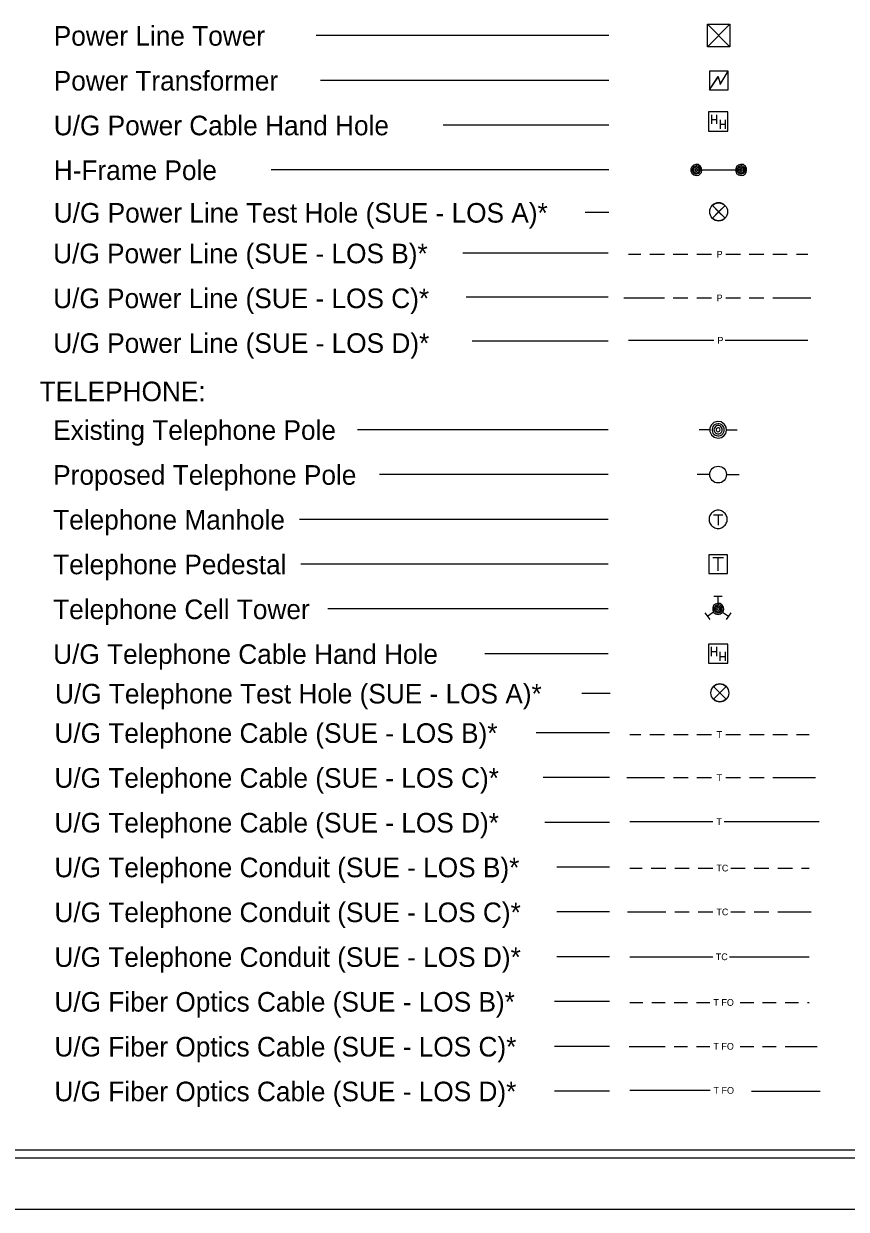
# Model space of a CAD drawing. Extents: x 2594871.4 to 2594905.1, y 784137.6 to 784159.6.
# Drawn here: x 2594889.82 to 2594897.02, y 784137.56 to 784147.95 of the extents above; entities that cross this region are included whole.
import ezdxf

# ---------------------------------------------------------------- set-up
doc = ezdxf.new("R2010")
doc.units = 0
for name, color, linetype in [('Default', 7, 'Continuous'), ('Sheet Plot Border Inside CELL', 7, 'Continuous'), ('Sheet Plot Border Outside CELL', 7, 'Continuous'), ('Sheet Symbology CELL', 7, 'Continuous')]:
    doc.layers.add(name, color=color, linetype=linetype)

msp = doc.modelspace()

# ---------------------------------------------------------------- linework, layer by layer
at = {"layer": 'Default'}
for p, q in [((2594896, 784147.941), (2594895.804, 784147.745)), ((2594896, 784147.745), (2594895.804, 784147.941)), ((2594894.94, 784147.842), (2594892.377, 784147.842)), ((2594894.94, 784147.45), (2594892.417, 784147.45)), ((2594895.837, 784147.148), (2594895.837, 784147.069)), ((2594895.883, 784147.148), (2594895.883, 784147.069)), ((2594894.94, 784147.058), (2594893.491, 784147.058)), ((2594895.837, 784147.108), (2594895.883, 784147.108)), ((2594895.913, 784147.105), (2594895.913, 784147.026)), ((2594895.913, 784147.065), (2594895.958, 784147.065)), ((2594895.958, 784147.105), (2594895.958, 784147.026)), ((2594894.94, 784146.666), (2594891.984, 784146.666)), ((2594895.706, 784146.666), (2594896.098, 784146.666)), ((2594894.94, 784146.293), (2594894.732, 784146.293)), ((2594894.935, 784145.937), (2594893.662, 784145.937)), ((2594895.112, 784145.927), (2594895.22, 784145.927)), ((2594895.298, 784145.927), (2594895.426, 784145.927)), ((2594895.504, 784145.927), (2594895.632, 784145.927)), ((2594895.71, 784145.927), (2594895.837, 784145.927)), ((2594895.963, 784145.927), (2594896.091, 784145.927)), ((2594896.169, 784145.927), (2594896.296, 784145.927)), ((2594896.375, 784145.927), (2594896.502, 784145.927)), ((2594896.581, 784145.927), (2594896.681, 784145.927)), ((2594894.935, 784145.552), (2594893.692, 784145.552)), ((2594895.072, 784145.545), (2594895.426, 784145.545)), ((2594895.504, 784145.545), (2594895.632, 784145.545)), ((2594895.71, 784145.545), (2594895.837, 784145.545)), ((2594895.963, 784145.545), (2594896.091, 784145.545)), ((2594896.169, 784145.545), (2594896.296, 784145.545)), ((2594896.375, 784145.545), (2594896.709, 784145.545)), ((2594894.935, 784145.167), (2594893.744, 784145.167)), ((2594895.112, 784145.173), (2594895.859, 784145.173)), ((2594895.957, 784145.173), (2594896.681, 784145.173)), ((2594894.935, 784144.39), (2594892.74, 784144.39)), ((2594895.824, 784144.39), (2594895.73, 784144.39)), ((2594895.969, 784144.39), (2594896.063, 784144.39)), ((2594894.935, 784143.997), (2594892.933, 784143.997)), ((2594895.824, 784143.997), (2594895.713, 784143.997)), ((2594895.971, 784143.997), (2594896.081, 784143.997)), ((2594894.935, 784143.605), (2594892.231, 784143.605)), ((2594895.937, 784143.642), (2594895.856, 784143.642)), ((2594895.896, 784143.642), (2594895.896, 784143.553)), ((2594894.935, 784143.213), (2594892.244, 784143.213)), ((2594895.85, 784143.272), (2594895.942, 784143.272)), ((2594895.896, 784143.154), (2594895.896, 784143.272)), ((2594895.86, 784142.931), (2594895.933, 784142.931)), ((2594895.896, 784142.869), (2594895.896, 784142.931)), ((2594894.935, 784142.82), (2594892.479, 784142.82)), ((2594895.827, 784142.727), (2594895.784, 784142.787)), ((2594895.857, 784142.793), (2594895.806, 784142.757)), ((2594895.936, 784142.793), (2594895.987, 784142.757)), ((2594896.008, 784142.787), (2594895.966, 784142.727)), ((2594895.836, 784142.487), (2594895.836, 784142.408)), ((2594895.881, 784142.487), (2594895.881, 784142.408)), ((2594894.935, 784142.428), (2594893.855, 784142.428)), ((2594895.836, 784142.447), (2594895.881, 784142.447)), ((2594895.912, 784142.444), (2594895.912, 784142.365)), ((2594895.912, 784142.404), (2594895.957, 784142.404)), ((2594895.957, 784142.444), (2594895.957, 784142.365)), ((2594894.951, 784142.081), (2594894.703, 784142.081)), ((2594894.946, 784141.736), (2594894.303, 784141.736)), ((2594895.122, 784141.72), (2594895.221, 784141.72)), ((2594895.299, 784141.72), (2594895.427, 784141.72)), ((2594895.505, 784141.72), (2594895.633, 784141.72)), ((2594895.711, 784141.72), (2594895.839, 784141.72)), ((2594895.964, 784141.72), (2594896.092, 784141.72)), ((2594896.17, 784141.72), (2594896.298, 784141.72)), ((2594896.376, 784141.72), (2594896.504, 784141.72)), ((2594896.582, 784141.72), (2594896.692, 784141.72)), ((2594894.946, 784141.343), (2594894.365, 784141.343)), ((2594895.098, 784141.343), (2594895.427, 784141.343)), ((2594895.505, 784141.343), (2594895.633, 784141.343)), ((2594895.711, 784141.343), (2594895.839, 784141.343)), ((2594895.964, 784141.343), (2594896.092, 784141.343)), ((2594896.17, 784141.343), (2594896.298, 784141.343)), ((2594896.376, 784141.343), (2594896.75, 784141.343)), ((2594894.946, 784140.951), (2594894.38, 784140.951)), ((2594895.122, 784140.958), (2594895.851, 784140.958)), ((2594895.949, 784140.958), (2594896.78, 784140.958)), ((2594894.946, 784140.559), (2594894.485, 784140.559)), ((2594895.122, 784140.55), (2594895.232, 784140.55)), ((2594895.31, 784140.55), (2594895.438, 784140.55)), ((2594895.516, 784140.55), (2594895.644, 784140.55)), ((2594895.722, 784140.55), (2594895.85, 784140.55)), ((2594896.007, 784140.55), (2594896.134, 784140.55)), ((2594896.213, 784140.55), (2594896.34, 784140.55)), ((2594896.419, 784140.55), (2594896.546, 784140.55)), ((2594896.625, 784140.55), (2594896.692, 784140.55)), ((2594894.946, 784140.166), (2594894.485, 784140.166)), ((2594895.104, 784140.166), (2594895.438, 784140.166)), ((2594895.516, 784140.166), (2594895.644, 784140.166)), ((2594895.722, 784140.166), (2594895.85, 784140.166)), ((2594896.007, 784140.166), (2594896.134, 784140.166)), ((2594896.213, 784140.166), (2594896.34, 784140.166)), ((2594896.419, 784140.166), (2594896.71, 784140.166)), ((2594894.946, 784139.774), (2594894.485, 784139.774)), ((2594895.122, 784139.773), (2594895.85, 784139.773)), ((2594895.997, 784139.773), (2594896.692, 784139.773)), ((2594894.946, 784139.382), (2594894.463, 784139.382)), ((2594895.122, 784139.373), (2594895.237, 784139.373)), ((2594895.315, 784139.373), (2594895.433, 784139.373)), ((2594895.512, 784139.373), (2594895.629, 784139.373)), ((2594895.708, 784139.373), (2594895.825, 784139.373)), ((2594896.09, 784139.373), (2594896.208, 784139.373)), ((2594896.286, 784139.373), (2594896.404, 784139.373)), ((2594896.483, 784139.373), (2594896.6, 784139.373)), ((2594896.679, 784139.373), (2594896.692, 784139.373)), ((2594894.946, 784138.989), (2594894.463, 784138.989)), ((2594895.119, 784138.989), (2594895.433, 784138.989)), ((2594895.512, 784138.989), (2594895.629, 784138.989)), ((2594895.708, 784138.989), (2594895.825, 784138.989)), ((2594896.09, 784138.989), (2594896.208, 784138.989)), ((2594896.286, 784138.989), (2594896.404, 784138.989)), ((2594896.483, 784138.989), (2594896.763, 784138.989)), ((2594894.946, 784138.597), (2594894.463, 784138.597)), ((2594895.122, 784138.604), (2594895.826, 784138.604)), ((2594896.189, 784138.596), (2594896.79, 784138.596))]:
    msp.add_line(p, q, dxfattribs=at)
for points in [[(2594896, 784147.745), (2594895.804, 784147.745), (2594895.804, 784147.941), (2594896, 784147.941), (2594896, 784147.745), (2594895.804, 784147.745), (2594895.804, 784147.941), (2594896, 784147.941), (2594896, 784147.745)], [(2594895.82, 784147.368), (2594895.897, 784147.479), (2594895.916, 784147.419), (2594895.983, 784147.532)], [(2594895.82, 784147.368), (2594895.898, 784147.484), (2594895.915, 784147.414), (2594895.983, 784147.532)], [(2594895.82, 784147.368), (2594895.983, 784147.368), (2594895.983, 784147.532), (2594895.82, 784147.532), (2594895.82, 784147.368)], [(2594895.813, 784147.004), (2594895.982, 784147.004), (2594895.982, 784147.173), (2594895.813, 784147.173), (2594895.813, 784147.004)], [(2594895.741, 784146.666), (2594895.74, 784146.674), (2594895.737, 784146.682), (2594895.733, 784146.689), (2594895.727, 784146.694), (2594895.72, 784146.698), (2594895.711, 784146.7), (2594895.704, 784146.701), (2594895.695, 784146.699), (2594895.687, 784146.696), (2594895.681, 784146.692), (2594895.676, 784146.685), (2594895.672, 784146.678), (2594895.67, 784146.669), (2594895.67, 784146.662), (2594895.672, 784146.653), (2594895.676, 784146.646), (2594895.681, 784146.639), (2594895.687, 784146.635), (2594895.695, 784146.632), (2594895.704, 784146.63), (2594895.711, 784146.631), (2594895.72, 784146.633), (2594895.727, 784146.637), (2594895.733, 784146.642), (2594895.737, 784146.649), (2594895.74, 784146.657), (2594895.741, 784146.666)], [(2594895.73, 784146.666), (2594895.729, 784146.672), (2594895.726, 784146.679), (2594895.721, 784146.684), (2594895.715, 784146.688), (2594895.709, 784146.69), (2594895.702, 784146.69), (2594895.696, 784146.688), (2594895.69, 784146.684), (2594895.685, 784146.679), (2594895.682, 784146.672), (2594895.681, 784146.666), (2594895.682, 784146.659), (2594895.685, 784146.652), (2594895.69, 784146.647), (2594895.696, 784146.643), (2594895.702, 784146.641), (2594895.709, 784146.641), (2594895.715, 784146.643), (2594895.721, 784146.647), (2594895.726, 784146.652), (2594895.729, 784146.659), (2594895.73, 784146.666)], [(2594895.717, 784146.666), (2594895.716, 784146.67), (2594895.713, 784146.674), (2594895.709, 784146.676), (2594895.705, 784146.677), (2594895.7, 784146.675), (2594895.696, 784146.672), (2594895.694, 784146.668), (2594895.694, 784146.664), (2594895.696, 784146.659), (2594895.7, 784146.656), (2594895.705, 784146.654), (2594895.709, 784146.655), (2594895.713, 784146.657), (2594895.716, 784146.661), (2594895.717, 784146.666)], [(2594896.134, 784146.666), (2594896.133, 784146.674), (2594896.13, 784146.682), (2594896.125, 784146.689), (2594896.119, 784146.694), (2594896.112, 784146.698), (2594896.104, 784146.7), (2594896.096, 784146.701), (2594896.087, 784146.699), (2594896.079, 784146.696), (2594896.074, 784146.692), (2594896.068, 784146.685), (2594896.064, 784146.678), (2594896.062, 784146.669), (2594896.062, 784146.662), (2594896.064, 784146.653), (2594896.068, 784146.646), (2594896.074, 784146.639), (2594896.079, 784146.635), (2594896.087, 784146.632), (2594896.096, 784146.63), (2594896.104, 784146.631), (2594896.112, 784146.633), (2594896.119, 784146.637), (2594896.125, 784146.642), (2594896.13, 784146.649), (2594896.133, 784146.657), (2594896.134, 784146.666)], [(2594896.122, 784146.666), (2594896.121, 784146.672), (2594896.118, 784146.679), (2594896.113, 784146.684), (2594896.108, 784146.688), (2594896.102, 784146.69), (2594896.094, 784146.69), (2594896.088, 784146.688), (2594896.082, 784146.684), (2594896.078, 784146.679), (2594896.075, 784146.672), (2594896.074, 784146.666), (2594896.075, 784146.659), (2594896.078, 784146.652), (2594896.082, 784146.647), (2594896.088, 784146.643), (2594896.094, 784146.641), (2594896.102, 784146.641), (2594896.108, 784146.643), (2594896.113, 784146.647), (2594896.118, 784146.652), (2594896.121, 784146.659), (2594896.122, 784146.666)], [(2594896.109, 784146.666), (2594896.108, 784146.67), (2594896.106, 784146.674), (2594896.102, 784146.676), (2594896.097, 784146.677), (2594896.092, 784146.675), (2594896.088, 784146.672), (2594896.086, 784146.668), (2594896.086, 784146.664), (2594896.088, 784146.659), (2594896.092, 784146.656), (2594896.097, 784146.654), (2594896.102, 784146.655), (2594896.106, 784146.657), (2594896.108, 784146.661), (2594896.109, 784146.666)], [(2594895.957, 784146.355), (2594895.846, 784146.244), (2594895.901, 784146.299), (2594895.846, 784146.355), (2594895.957, 784146.244)], [(2594895.846, 784146.355), (2594895.901, 784146.299), (2594895.957, 784146.355)], [(2594895.957, 784146.244), (2594895.901, 784146.299), (2594895.846, 784146.244)], [(2594895.95, 784144.39), (2594895.948, 784144.403), (2594895.944, 784144.414), (2594895.937, 784144.424), (2594895.928, 784144.433), (2594895.918, 784144.439), (2594895.905, 784144.442), (2594895.893, 784144.443), (2594895.88, 784144.44), (2594895.869, 784144.436), (2594895.86, 784144.429), (2594895.851, 784144.419), (2594895.846, 784144.408), (2594895.843, 784144.395), (2594895.843, 784144.384), (2594895.846, 784144.371), (2594895.851, 784144.361), (2594895.86, 784144.35), (2594895.869, 784144.343), (2594895.88, 784144.339), (2594895.893, 784144.336), (2594895.905, 784144.337), (2594895.918, 784144.34), (2594895.928, 784144.346), (2594895.937, 784144.355), (2594895.944, 784144.365), (2594895.948, 784144.377), (2594895.95, 784144.39)], [(2594895.933, 784144.39), (2594895.931, 784144.4), (2594895.927, 784144.41), (2594895.919, 784144.417), (2594895.911, 784144.423), (2594895.902, 784144.426), (2594895.891, 784144.426), (2594895.882, 784144.423), (2594895.873, 784144.417), (2594895.866, 784144.41), (2594895.862, 784144.4), (2594895.86, 784144.39), (2594895.862, 784144.379), (2594895.866, 784144.369), (2594895.873, 784144.362), (2594895.882, 784144.356), (2594895.891, 784144.353), (2594895.902, 784144.353), (2594895.911, 784144.356), (2594895.919, 784144.362), (2594895.927, 784144.369), (2594895.931, 784144.379), (2594895.933, 784144.39)], [(2594895.914, 784144.39), (2594895.912, 784144.397), (2594895.908, 784144.403), (2594895.902, 784144.406), (2594895.895, 784144.407), (2594895.888, 784144.404), (2594895.882, 784144.4), (2594895.879, 784144.393), (2594895.879, 784144.387), (2594895.882, 784144.379), (2594895.888, 784144.375), (2594895.895, 784144.372), (2594895.902, 784144.374), (2594895.908, 784144.377), (2594895.912, 784144.382), (2594895.914, 784144.39)], [(2594895.896, 784143.685), (2594895.886, 784143.684), (2594895.877, 784143.682), (2594895.867, 784143.679), (2594895.858, 784143.674), (2594895.85, 784143.669), (2594895.842, 784143.663), (2594895.835, 784143.655), (2594895.829, 784143.648), (2594895.824, 784143.639), (2594895.821, 784143.629), (2594895.819, 784143.62), (2594895.817, 784143.61), (2594895.817, 784143.6), (2594895.819, 784143.59), (2594895.821, 784143.58), (2594895.824, 784143.571), (2594895.829, 784143.562), (2594895.835, 784143.555), (2594895.842, 784143.547), (2594895.85, 784143.541), (2594895.858, 784143.536), (2594895.867, 784143.531), (2594895.877, 784143.528), (2594895.887, 784143.526), (2594895.896, 784143.525), (2594895.907, 784143.526), (2594895.916, 784143.528), (2594895.926, 784143.531), (2594895.935, 784143.536), (2594895.943, 784143.541), (2594895.95, 784143.547), (2594895.958, 784143.555), (2594895.963, 784143.562), (2594895.968, 784143.571), (2594895.972, 784143.581), (2594895.974, 784143.59), (2594895.975, 784143.6), (2594895.975, 784143.61), (2594895.974, 784143.62), (2594895.972, 784143.63), (2594895.968, 784143.639), (2594895.963, 784143.648), (2594895.958, 784143.655), (2594895.95, 784143.663), (2594895.943, 784143.669), (2594895.935, 784143.674), (2594895.926, 784143.679), (2594895.916, 784143.682), (2594895.906, 784143.684), (2594895.896, 784143.685)], [(2594895.814, 784143.13), (2594895.979, 784143.13), (2594895.979, 784143.295), (2594895.814, 784143.295), (2594895.814, 784143.13)], [(2594895.932, 784142.82), (2594895.931, 784142.829), (2594895.928, 784142.837), (2594895.923, 784142.844), (2594895.918, 784142.849), (2594895.911, 784142.853), (2594895.902, 784142.855), (2594895.894, 784142.856), (2594895.886, 784142.854), (2594895.878, 784142.851), (2594895.872, 784142.846), (2594895.866, 784142.84), (2594895.863, 784142.833), (2594895.861, 784142.824), (2594895.861, 784142.816), (2594895.863, 784142.808), (2594895.866, 784142.801), (2594895.872, 784142.794), (2594895.878, 784142.789), (2594895.886, 784142.787), (2594895.894, 784142.785), (2594895.902, 784142.786), (2594895.911, 784142.788), (2594895.918, 784142.791), (2594895.923, 784142.797), (2594895.928, 784142.804), (2594895.931, 784142.812), (2594895.932, 784142.82)], [(2594895.92, 784142.82), (2594895.919, 784142.827), (2594895.917, 784142.834), (2594895.912, 784142.839), (2594895.906, 784142.843), (2594895.9, 784142.844), (2594895.892, 784142.844), (2594895.887, 784142.843), (2594895.881, 784142.839), (2594895.876, 784142.834), (2594895.873, 784142.827), (2594895.872, 784142.82), (2594895.873, 784142.814), (2594895.876, 784142.807), (2594895.881, 784142.802), (2594895.887, 784142.798), (2594895.892, 784142.796), (2594895.9, 784142.796), (2594895.906, 784142.798), (2594895.912, 784142.802), (2594895.917, 784142.807), (2594895.919, 784142.814), (2594895.92, 784142.82)], [(2594895.908, 784142.82), (2594895.907, 784142.825), (2594895.904, 784142.829), (2594895.9, 784142.831), (2594895.895, 784142.832), (2594895.891, 784142.83), (2594895.887, 784142.827), (2594895.885, 784142.822), (2594895.885, 784142.818), (2594895.887, 784142.814), (2594895.891, 784142.811), (2594895.895, 784142.809), (2594895.9, 784142.81), (2594895.904, 784142.812), (2594895.907, 784142.816), (2594895.908, 784142.82)], [(2594895.812, 784142.344), (2594895.981, 784142.344), (2594895.981, 784142.512), (2594895.812, 784142.512), (2594895.812, 784142.344)], [(2594895.966, 784142.14), (2594895.855, 784142.03), (2594895.911, 784142.085), (2594895.855, 784142.14), (2594895.966, 784142.03)], [(2594895.855, 784142.14), (2594895.911, 784142.085), (2594895.966, 784142.14)], [(2594895.966, 784142.03), (2594895.911, 784142.085), (2594895.855, 784142.03)]]:
    msp.add_lwpolyline(points, dxfattribs=at)
for points in [[(2594895.706, 784146.617), (2594895.726, 784146.621), (2594895.739, 784146.631), (2594895.75, 784146.644), (2594895.754, 784146.663), (2594895.752, 784146.68), (2594895.742, 784146.697), (2594895.723, 784146.712), (2594895.701, 784146.714), (2594895.681, 784146.708), (2594895.666, 784146.694), (2594895.658, 784146.676), (2594895.658, 784146.655), (2594895.666, 784146.637), (2594895.683, 784146.622)], [(2594896.098, 784146.617), (2594896.118, 784146.621), (2594896.132, 784146.631), (2594896.142, 784146.644), (2594896.146, 784146.663), (2594896.144, 784146.68), (2594896.135, 784146.697), (2594896.115, 784146.712), (2594896.093, 784146.714), (2594896.074, 784146.708), (2594896.058, 784146.694), (2594896.051, 784146.676), (2594896.051, 784146.655), (2594896.058, 784146.637), (2594896.076, 784146.622)], [(2594895.896, 784144.317), (2594895.927, 784144.323), (2594895.947, 784144.337), (2594895.963, 784144.358), (2594895.969, 784144.385), (2594895.966, 784144.411), (2594895.951, 784144.437), (2594895.922, 784144.459), (2594895.889, 784144.462), (2594895.86, 784144.453), (2594895.837, 784144.433), (2594895.825, 784144.406), (2594895.825, 784144.374), (2594895.837, 784144.346), (2594895.863, 784144.324)], [(2594895.896, 784142.772), (2594895.917, 784142.776), (2594895.93, 784142.786), (2594895.941, 784142.799), (2594895.945, 784142.817), (2594895.943, 784142.835), (2594895.933, 784142.852), (2594895.914, 784142.867), (2594895.892, 784142.869), (2594895.872, 784142.863), (2594895.857, 784142.849), (2594895.849, 784142.831), (2594895.849, 784142.81), (2594895.857, 784142.791), (2594895.874, 784142.777)]]:
    msp.add_lwpolyline(points, close=True, dxfattribs=at)
for centre, radius in [((2594895.901, 784146.299), 0.0784), ((2594895.896, 784143.997), 0.0736), ((2594895.911, 784142.085), 0.0784)]:
    msp.add_circle(centre, radius, dxfattribs=at)
for centre, start, end in [((2594895.901, 784146.299), 45, 135), ((2594895.901, 784146.299), 225, 315), ((2594895.911, 784142.085), 45, 135), ((2594895.911, 784142.085), 225, 315)]:
    msp.add_arc(centre, 0.0784, start, end, dxfattribs=at)
at = {"layer": 'Sheet Plot Border Inside CELL'}
msp.add_lwpolyline([(2594871.632, 784138.011), (2594904.962, 784138.011), (2594904.962, 784159.113), (2594871.632, 784159.113)], close=True, dxfattribs=at)
at = {"layer": 'Sheet Plot Border Outside CELL'}
msp.add_lwpolyline([(2594905.052, 784159.562), (2594871.372, 784159.562), (2594871.372, 784137.562), (2594905.052, 784137.562)], close=True, dxfattribs=at)
at = {"layer": 'Sheet Symbology CELL'}
msp.add_lwpolyline([(2594904.712, 784159.062), (2594874.712, 784159.062), (2594874.712, 784138.082), (2594904.712, 784138.082)], close=True, dxfattribs=at)

# ---------------------------------------------------------------- texts
at = {"layer": 'Default'}
for s, height, p in [('Power Line Tower', 0.17164, (2594890.081, 784147.754)), ('Power Transformer', 0.17164, (2594890.081, 784147.361)), ('U/G Power Cable Hand Hole', 0.17164, (2594890.081, 784146.969)), ('H-Frame Pole', 0.17164, (2594890.081, 784146.577)), ('U/G Power Line Test Hole (SUE - LOS A)*', 0.17164, (2594890.081, 784146.204)), ('U/G Power Line (SUE - LOS B)*', 0.17164, (2594890.076, 784145.848)), ('P', 0.0588, (2594895.883, 784145.898)), ('U/G Power Line (SUE - LOS C)*', 0.17164, (2594890.076, 784145.455)), ('P', 0.0588, (2594895.883, 784145.515)), ('U/G Power Line (SUE - LOS D)*', 0.17164, (2594890.077, 784145.063)), ('P', 0.0588, (2594895.89, 784145.143)), ('TELEPHONE:', 0.1716, (2594889.957, 784144.64)), ('Existing Telephone Pole', 0.17164, (2594890.076, 784144.301)), ('Proposed Telephone Pole', 0.17164, (2594890.076, 784143.908)), ('Telephone Manhole', 0.17164, (2594890.076, 784143.516)), ('Telephone Pedestal', 0.17164, (2594890.076, 784143.124)), ('Telephone Cell Tower', 0.17164, (2594890.076, 784142.731)), ('U/G Telephone Cable Hand Hole', 0.17164, (2594890.076, 784142.339)), ('U/G Telephone Test Hole (SUE - LOS A)*', 0.17164, (2594890.092, 784141.992)), ('U/G Telephone Cable (SUE - LOS B)*', 0.17164, (2594890.087, 784141.647)), ('T', 0.0588, (2594895.883, 784141.691)), ('U/G Telephone Cable (SUE - LOS C)*', 0.17164, (2594890.087, 784141.254)), ('T', 0.0588, (2594895.883, 784141.314)), ('U/G Telephone Cable (SUE - LOS D)*', 0.17164, (2594890.087, 784140.862)), ('T', 0.0588, (2594895.881, 784140.928)), ('U/G Telephone Conduit (SUE - LOS B)*', 0.17164, (2594890.087, 784140.47)), ('TC', 0.0588, (2594895.881, 784140.521)), ('U/G Telephone Conduit (SUE - LOS C)*', 0.17164, (2594890.087, 784140.077)), ('TC', 0.0588, (2594895.881, 784140.137)), ('U/G Telephone Conduit (SUE - LOS D)*', 0.17164, (2594890.087, 784139.685)), ('TC', 0.0588, (2594895.876, 784139.744)), ('U/G Fiber Optics Cable (SUE - LOS B)*', 0.17164, (2594890.087, 784139.293)), ('T FO', 0.0588, (2594895.855, 784139.344)), ('U/G Fiber Optics Cable (SUE - LOS C)*', 0.17164, (2594890.087, 784138.9)), ('T FO', 0.0588, (2594895.855, 784138.96)), ('U/G Fiber Optics Cable (SUE - LOS D)*', 0.17164, (2594890.087, 784138.508)), ('T FO', 0.0588, (2594895.856, 784138.574))]:
    msp.add_text(s, height=height, rotation=360, dxfattribs=at).set_placement(p)

doc.saveas('drawing.dxf')
